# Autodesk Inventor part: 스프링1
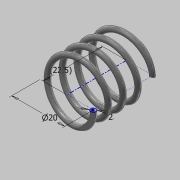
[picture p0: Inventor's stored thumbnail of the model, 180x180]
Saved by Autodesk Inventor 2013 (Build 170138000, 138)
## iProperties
Created: 2016-07
Part Number: 스프링1
Material: 스테인리스강
Document SubType Name: Modeling
Designer: dgall
Density: 8.08 g/cm^3
Mass: 6.26715 g
Surface Area: 15.7465 cm^2
Volume: 0.775637 cm^3
Author: dgall
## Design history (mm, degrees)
sketch "스케치1"
  geometry: L1 (0, 0)-(10, 0); L2 (10, 0)-(10, 22.5); L3 (10, 22.5)-(0, 22.5); L4 (0, 22.5)-(0, 0); C1 r 1 at (10, 0)
  constraints: 8 end point, 2 parallel, 1 centre point, 1 coincident, 1 horizontal, 1 perpendicular
  dimensions: "d0" = 20 diameter of L2 L4; "d2" = 22.5 distance of L3.end L1.start (derived); "d3" = 2 diameter of C1
feature "코일1" pitch "d4" = 10; turns "d6" = 4; dims "d5" = 22.5 (= d2), "d7" = 0, angle "d8" = 90 deg, angle "d9" = 90 deg, "d10" = 0, "d11" = 0
feature "분할1"
node "작업 평면1"
feature "분할2"
node "솔리드1"
